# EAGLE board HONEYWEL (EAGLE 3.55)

No outline drawn. Coordinates in mm, seen from the top.
Copper layers used: 

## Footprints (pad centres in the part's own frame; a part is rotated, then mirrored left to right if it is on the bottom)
50-001 = drill 0.7 pad 1.27 round:  -15.24,10.16;  -15.24,7.62;  -15.24,5.08;  -15.24,2.54;  -15.24,0;  -15.24,-2.54;  -15.24,-5.08;  -15.24,-7.62;  -15.24,-10.16 | hole 1.422: 5.08,10.16; 5.08,-10.16
 = drill 0.508 pad 1.778 round:  6.706,-1.27;  6.706,1.27;  4.166,1.27;  4.166,-1.27 | hole 1.321: -0.152,-4.763; -0.152,4.763
UNEF = drill 0.508 pad 1.778 round:  6.706,-1.27;  6.706,1.27;  4.166,1.27;  4.166,-1.27 | hole 1.321: -0.152,-4.763; -0.152,4.763
S = drill 0.813 pad 1.6 octagon:  0,1.905;  1.905,0;  0,-1.905
D1300 = drill 0.61 pad 1.27 octagon:  -6.985,1.27;  -8.255,0;  -6.985,-1.27;  -5.715,0 | hole 1.778: 0,-4.763; 0,4.763; 0,-4.763; 0,4.763
E-3XX = drill 0.813 pad 1.397 octagon:  -1.27,1.27;  -1.27,-1.27;  1.27,-1.27
M2451 = drill 0.7 pad 1.27 round:  15.24,-10.16;  15.24,-7.62;  15.24,-5.08;  15.24,-2.54;  15.24,0;  15.24,2.54;  15.24,5.08;  15.24,7.62;  15.24,10.16 | hole 1.422: -5.08,-10.16; -5.08,10.16
M-SMA = drill 0.813 pad 1.397 round:  -8.89,-3.81;  -6.35,-3.81;  -3.81,-3.81;  -1.27,-3.81;  1.27,-3.81;  3.81,-3.81;  6.35,-3.81;  8.89,-3.81;  8.89,3.81;  6.35,3.81;  3.81,3.81;  1.27,3.81;  -1.27,3.81;  -3.81,3.81;  -6.35,3.81;  -8.89,3.81
M-ST = drill 0.813 pad 1.397 round:  -8.89,-3.81;  -6.35,-3.81;  -3.81,-3.81;  -1.27,-3.81;  1.27,-3.81;  3.81,-3.81;  6.35,-3.81;  8.89,-3.81;  8.89,3.81;  6.35,3.81;  3.81,3.81;  1.27,3.81;  -1.27,3.81;  -3.81,3.81;  -6.35,3.81;  -8.89,3.81
X6-200 = drill 0.7 pad 1.27 round:  1.27,-3.81;  1.27,-1.27;  1.27,1.27;  1.27,3.81;  -1.27,3.81;  -1.27,1.27;  -1.27,-1.27;  -1.27,-3.81 | hole 1.7: -3.87,-4.6; -3.87,4.6
X6-548 = drill 0.7 pad 1.27 round:  1.27,-3.81;  1.27,-1.27;  1.27,1.27;  1.27,3.81;  -1.27,3.81;  -1.27,1.27;  -1.27,-1.27;  -1.27,-3.81 | hole 1.7: -3.87,-4.6; -3.87,4.6
ST = drill 0.7 pad 1.778 round:  2.54,-3.81;  2.54,-1.27;  2.54,1.27;  2.54,3.81;  -2.54,3.81;  -2.54,1.27;  -2.54,-1.27;  -2.54,-3.81
STOPHO = drill 0.7 pad 1.778 round:  2.54,-3.81;  2.54,-1.27;  2.54,1.27;  2.54,3.81;  -2.54,3.81;  -2.54,1.27;  -2.54,-1.27;  -2.54,-3.81
FIBER = drill 0.7 pad 1.778 round:  2.54,-3.81;  2.54,-1.27;  2.54,1.27;  2.54,3.81;  -2.54,3.81;  -2.54,1.27;  -2.54,-1.27;  -2.54,-3.81
A-PCB = drill 0.61 pad 1.397 octagon:  -7.62,-1.27;  -6.35,0;  -7.62,1.27 | hole 1.778: 0,-4.763; 0,4.763
2 = drill 0.61 pad 1.27 octagon:  -6.985,-1.27;  -5.715,0;  -6.985,1.27 | hole 1.778: 0,-4.763; 0,4.763
3894-3 = drill 0.61 pad 1.397 octagon:  -6.35,1.27;  -7.62,0;  -6.35,-1.27;  -5.08,0 | hole 1.778: -0.889,-4.763; -0.889,4.763
-LP = drill 0.61 pad 1.27 octagon:  -5.08,-1.27;  -3.81,0;  -5.08,1.27 | hole 1.778: 0,-4.763; 0,4.763
-LPL = drill 0.61 pad 1.397 octagon:  -5.08,-1.27;  -3.81,0;  -5.08,1.27 | hole 1.778: 0,-4.763; 0,4.763
-PCB = drill 0.61 pad 1.397 octagon:  -6.35,-1.27;  -5.08,0;  -6.35,1.27 | hole 1.778: 0,-4.763; 0,4.763
-SINGL = drill 0.61 pad 1.397 octagon:  -3.81,-1.27;  -2.54,0;  -3.81,1.27
LP2 = drill 0.61 pad 1.397 octagon:  -5.08,1.27;  -5.08,-1.27;  -7.62,-1.27;  -7.62,1.27 | hole 1.778: -0.889,-4.763; -0.889,4.763; -0.889,-4.763; -0.889,4.763
LP4 = drill 0.61 pad 1.27 octagon:  -5.08,-1.27;  -3.81,0;  -5.08,1.27;  -6.35,0 | hole 1.778: 0,-4.763; 0,4.763
LPBENT = drill 0.61 pad 1.397 octagon:  -5.08,1.27;  -5.08,-1.27;  -7.62,-1.27;  -7.62,1.27 | hole 1.778: -0.889,-4.763; -0.889,4.763
PF102 = drill 0.7 pad 1.778 round:  2.54,-3.81;  2.54,-1.27;  2.54,1.27;  2.54,3.81;  -2.54,3.81;  -2.54,1.27;  -2.54,-1.27;  -2.54,-3.81
PF201 = drill 0.7 pad 1.778 round:  2.54,-3.81;  2.54,-1.27;  2.54,1.27;  2.54,3.81;  -2.54,3.81;  -2.54,1.27;  -2.54,-1.27;  -2.54,-3.81
18-4 = drill 0.61 pad 1.016 round:  0,1.27;  -1.27,0;  0,-1.27;  1.27,0
18PL3 = drill 0.61 pad 1.016 round:  0,1.27;  -1.27,0;  0,-1.27
18PL4 = drill 0.61 pad 1.016 round:  0,1.27;  -1.27,0;  0,-1.27;  1.27,0
46-FW3 = drill 0.61 pad 1.27 round:  0,1.27;  -1.27,0;  0,-1.27
46-FW4 = drill 0.61 pad 1.27 round:  0,1.27;  -1.27,0;  0,-1.27;  1.27,0
46-LW3 = drill 0.61 pad 1.27 round:  0,1.27;  -1.27,0;  0,-1.27
46-LW4 = drill 0.61 pad 1.27 round:  0,1.27;  -1.27,0;  0,-1.27;  1.27,0
46-LX = drill 0.813 pad 1.676 octagon:  -1.27,1.27;  -1.27,-1.27;  1.27,-1.27
46-P3 = drill 0.61 pad 1.27 octagon:  -1.27,1.27;  -1.27,-1.27;  1.27,-1.27
-18 = drill 0.813 pad 1.6 octagon:  -1.27,-1.27;  1.27,-1.27;  1.27,1.27
PFTTP = drill 1.016 pad 1.778 octagon:  -5.08,-9.525;  -2.54,-9.525;  0,-9.525;  2.54,-9.525;  5.08,-9.525 | hole 3.277: 0,9.525; -4.445,-4.445; 4.445,-4.445
PFTTP4 = drill 1.016 pad 1.778 octagon:  -26.873,0;  -24.333,0;  -21.793,0;  -19.253,0;  -16.713,0;  -12.344,0;  -9.804,0;  -7.264,0;  -4.724,0;  -2.184,0;  26.873,0;  24.333,0;  21.793,0;  19.253,0;  16.713,0;  12.344,0;  9.804,0;  7.264,0;  4.724,0;  2.184,0 | hole 3.277: -25.4,16.358; 0,16.358; 25.4,16.358

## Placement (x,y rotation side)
2450-001  [50-001]  59.69,229.87 270 top
F4  []  162.56,73.66 0 top
F4UNEF  [UNEF]  162.56,93.98 0 top
FRS  [S]  15.24,40.64 0 top
GFD1300  [D1300]  52.07,15.24 0 top
HFE-3XX  [E-3XX]  15.24,53.34 0 top
HFM2451  [M2451]  20.32,229.87 90 top
HFM-SMA  [M-SMA]  114.3,16.51 0 top
HFM-ST  [M-ST]  114.3,34.29 0 top
HFX6-200  [X6-200]  168.91,15.24 0 top
HFX6-548  [X6-548]  168.91,34.29 0 top
NGST  [ST]  167.64,53.34 0 top
NGSTOPHO  [STOPHO]  166.37,171.45 0 top
SCFIBER  [FIBER]  166.37,191.77 0 top
SMA-PCB  [A-PCB]  52.07,33.02 0 top
ST2  [2]  52.07,119.38 0 top
ST3894-3  [3894-3]  52.07,137.16 0 top
ST-LP  [-LP]  50.8,50.8 0 top
ST-LPL  [-LPL]  50.8,68.58 0 top
ST-PCB  [-PCB]  50.8,86.36 0 top
ST-SINGL  [-SINGL]  49.53,102.87 0 top
STLP2  [LP2]  52.07,154.94 0 top
STLP4  [LP4]  50.8,172.72 0 top
STLPBENT  [LPBENT]  52.07,190.5 0 top
STPF102  [PF102]  166.37,114.3 0 top
STPF201  [PF201]  166.37,132.08 0 top
STUNEF  [UNEF]  166.37,152.4 0 top
TO18-4  [18-4]  15.24,15.24 0 top
TO18PL3  [18PL3]  15.24,67.31 0 top
TO18PL4  [18PL4]  15.24,80.01 0 top
TO46-FW3  [46-FW3]  15.24,92.71 0 top
TO46-FW4  [46-FW4]  15.24,105.41 0 top
TO46-LW3  [46-LW3]  15.24,118.11 0 top
TO46-LW4  [46-LW4]  15.24,130.81 0 top
TO46-LX  [46-LX]  15.24,143.51 0 top
TO46-P3  [46-P3]  15.24,156.21 0 top
TO-18  [-18]  15.24,29.21 0 top
UTPFTTP  [PFTTP]  104.14,233.68 0 top
UTPFTTP1  [-35SC]  0,0 0 top
UTPFTTP4  [PFTTP4]  148.59,223.52 0 top

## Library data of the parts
2450-001 F4 F4UNEF FRS GFD1300 HFE-3XX HFM2451 HFM-SMA HFM-ST HFX6-200 HFX6-548 NGST NGSTOPHO SCFIBER SMA-PCB ST2 ST3894-3 ST-LP ST-LPL ST-PCB ST-SINGL STLP2 STLP4 STLPBENT STPF102 STPF201 STUNEF TO18-4 TO18PL3 TO18PL4 TO46-FW3 TO46-FW4 TO46-LW3 TO46-LW4 TO46-LX TO46-P3 TO-18 UTPFTTP UTPFTTP4 = HONEYWEL
UTPFTTP1 = frames

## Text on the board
tPlace: 39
